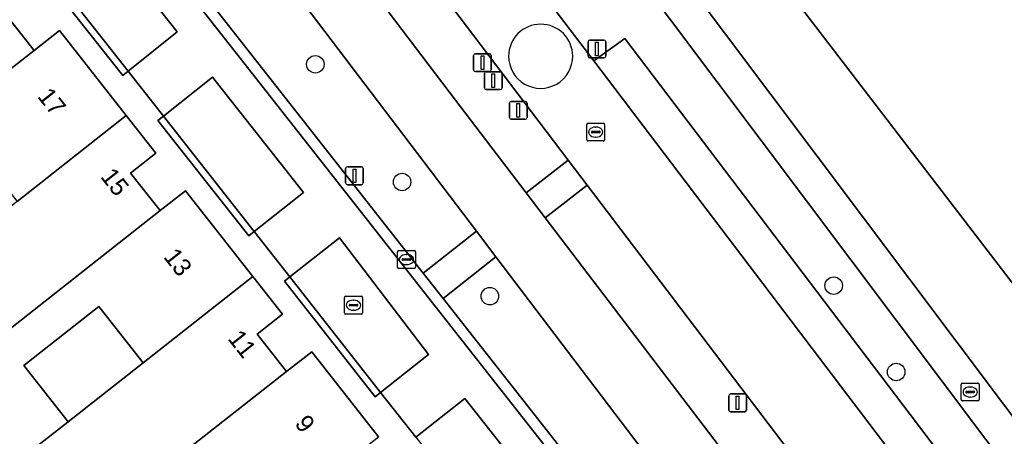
# Model space of a CAD drawing. Extents: x 156661 to 157576, y 383570 to 384425.
# Drawn here: x 157036.8 to 157091.8, y 383980.8 to 384004 of the extents above; entities that cross this region are included whole.
import ezdxf

# ---------------------------------------------------------------- set-up
doc = ezdxf.new("R2010")
doc.units = 0
for name, color, linetype in [('IMGEO_Afsluitpaal', 7, 'Continuous'), ('IMGEO_Berm_groen', 7, 'Continuous'), ('IMGEO_Boom', 7, 'Continuous'), ('IMGEO_Brandkraan', 7, 'Continuous'), ('IMGEO_Erf', 7, 'Continuous'), ('IMGEO_Fietspad_gesloten', 7, 'Continuous'), ('IMGEO_Groenvoorziening', 7, 'Continuous'), ('IMGEO_Kolk', 7, 'Continuous'), ('IMGEO_Lichtmast', 7, 'Continuous'), ('IMGEO_Muur', 7, 'Continuous'), ('IMGEO_Pand', 7, 'Continuous'), ('IMGEO_Pand_nummerreeks', 7, 'Continuous'), ('IMGEO_Parkeervlak_gesloten', 7, 'Continuous'), ('IMGEO_Rijbaan_lokaal_open', 7, 'Continuous'), ('IMGEO_Rioolput', 7, 'Continuous'), ('IMGEO_Voetpad_gesloten', 7, 'Continuous'), ('IMGEO_Voetpad_open', 7, 'Continuous')]:
    doc.layers.add(name, color=color, linetype=linetype)

msp = doc.modelspace()

# ---------------------------------------------------------------- linework, layer by layer
at = {"layer": 'IMGEO_Afsluitpaal'}
for p, q in [((157068.554, 384002.007), (157068.554, 384002.807)), ((157068.554, 384002.807), (157068.554, 384002.007)), ((157068.654, 384002.907), (157069.444, 384002.907)), ((157069.444, 384002.907), (157068.654, 384002.907)), ((157069.544, 384002.807), (157069.544, 384002.007)), ((157069.544, 384002.007), (157069.544, 384002.807)), ((157062.153, 384001.243), (157062.153, 384002.043)), ((157062.153, 384002.043), (157062.153, 384001.243)), ((157062.253, 384002.143), (157063.043, 384002.143)), ((157063.043, 384002.143), (157062.253, 384002.143)), ((157063.143, 384002.043), (157063.143, 384001.243)), ((157063.143, 384001.243), (157063.143, 384002.043)), ((157069.444, 384001.907), (157068.654, 384001.907)), ((157068.654, 384001.907), (157069.444, 384001.907)), ((157063.043, 384001.143), (157062.253, 384001.143)), ((157062.253, 384001.143), (157063.043, 384001.143)), ((157064.155, 383998.579), (157064.155, 383999.379)), ((157064.155, 383999.379), (157064.155, 383998.579)), ((157064.255, 383999.479), (157065.045, 383999.479)), ((157065.045, 383999.479), (157064.255, 383999.479)), ((157065.145, 383999.379), (157065.145, 383998.579)), ((157065.145, 383998.579), (157065.145, 383999.379)), ((157065.045, 383998.479), (157064.255, 383998.479)), ((157064.255, 383998.479), (157065.045, 383998.479))]:
    msp.add_line(p, q, dxfattribs=at)
for points in [[(157068.974, 384002.782), (157069.124, 384002.782), (157069.124, 384002.032), (157068.974, 384002.032), (157068.974, 384002.782)], [(157062.573, 384002.018), (157062.723, 384002.018), (157062.723, 384001.268), (157062.573, 384001.268), (157062.573, 384002.018)], [(157064.575, 383999.354), (157064.725, 383999.354), (157064.725, 383998.604), (157064.575, 383998.604), (157064.575, 383999.354)]]:
    msp.add_lwpolyline(points, dxfattribs=at)
for centre, start, end in [((157068.654, 384002.807), 90, 180), ((157068.654, 384002.807), 90, 180), ((157069.444, 384002.807), 0, 90), ((157069.444, 384002.807), 360, 90), ((157062.253, 384002.043), 90, 180), ((157062.253, 384002.043), 90, 180), ((157063.043, 384002.043), 0, 90), ((157063.043, 384002.043), 360, 90), ((157068.654, 384002.007), 180, 270), ((157068.654, 384002.007), 180, 270), ((157069.444, 384002.007), 270, 0), ((157069.444, 384002.007), 270, 0), ((157062.253, 384001.243), 180, 270), ((157062.253, 384001.243), 180, 270), ((157063.043, 384001.243), 270, 0), ((157063.043, 384001.243), 270, 0), ((157064.255, 383999.379), 90, 180), ((157064.255, 383999.379), 90, 180), ((157065.045, 383999.379), 0, 90), ((157065.045, 383999.379), 360, 90), ((157064.255, 383998.579), 180, 270), ((157064.255, 383998.579), 180, 270), ((157065.045, 383998.579), 270, 0), ((157065.045, 383998.579), 270, 0)]:
    msp.add_arc(centre, 0.1, start, end, dxfattribs=at)
at = {"layer": 'IMGEO_Berm_groen'}
for points in [[(157022.83, 384054.925), (157020.102, 384058.503), (157014.424, 384065.95), (157012.072, 384064.137), (157061.136, 383999.546), (157065.088, 383994.36), (157067.449, 383996.186), (157062.167, 384003.14)], [(157009.29, 384061.994), (157005.166, 384058.77), (157059.34, 383989.875), (157062.312, 383992.226)], [(157050.635, 384034.033), (157048.731, 384036.511), (157037.008, 384052.138), (157034.658, 384050.365), (157044.213, 384037.466), (157044.358, 384037.568), (157067.634, 384006.822), (157065.932, 384005.612), (157068.869, 384001.744), (157070.607, 384003.001), (157106.45, 383955.782), (157108.373, 383957.2)]]:
    msp.add_lwpolyline(points, close=True, dxfattribs=at)
for points in [[(157068.511, 383994.788), (157066.152, 383992.965), (157092.711, 383958.119)], [(157098.259, 383949.806), (157101.105, 383951.881), (157068.511, 383994.788)], [(157063.404, 383990.789), (157060.448, 383988.467), (157093.57, 383946.344), (157095.404, 383947.68)], [(157089.259, 383956.768), (157063.404, 383990.789)]]:
    msp.add_lwpolyline(points, dxfattribs=at)
at = {"layer": 'IMGEO_Boom'}
for centre in [(157053.305, 384001.553), (157058.156, 383994.971), (157082.287, 383989.179), (157063.064, 383988.589), (157085.787, 383984.352)]:
    msp.add_circle(centre, 0.489, dxfattribs=at)
at = {"layer": 'IMGEO_Brandkraan'}
for p, q in [((157089.496, 383983.733), (157090.348, 383983.733)), ((157089.421, 383982.807), (157089.421, 383983.659)), ((157089.68, 383983.227), (157089.68, 383983.239)), ((157090.118, 383983.19), (157089.72, 383983.19)), ((157089.723, 383983.276), (157090.121, 383983.276)), ((157089.909, 383983.513), (157089.934, 383983.513)), ((157090.164, 383983.239), (157090.164, 383983.227)), ((157090.422, 383983.659), (157090.422, 383982.807)), ((157090.348, 383982.733), (157089.496, 383982.733)), ((157089.932, 383982.953), (157089.907, 383982.953))]:
    msp.add_line(p, q, dxfattribs=at)
for points in [[(157089.496, 383983.733), (157090.348, 383983.733)], [(157089.421, 383982.807), (157089.421, 383983.659)], [(157090.422, 383983.659), (157090.422, 383982.807)], [(157090.348, 383982.733), (157089.496, 383982.733)]]:
    msp.add_lwpolyline(points, dxfattribs=at)
for centre, radius, start, end in [((157089.498, 383983.657), 0.0765, 91.552, 178.448), ((157089.498, 383983.657), 0.0765, 91.552, 178.448), ((157090.346, 383983.657), 0.0765, 1.552, 88.448), ((157090.346, 383983.657), 0.0765, 1.552, 88.448), ((157089.72, 383983.236), 0.0403, 85.8775, 175.7526), ((157089.717, 383983.226), 0.0366, 178.938, 274.7102), ((157090.121, 383983.233), 0.043, 264.8664, 352.4533), ((157090.125, 383983.238), 0.0386, 1.7309, 96.639), ((157089.498, 383982.809), 0.0765, 181.552, 268.448), ((157089.498, 383982.809), 0.0765, 181.552, 268.448), ((157090.346, 383982.809), 0.0765, 271.552, 358.448), ((157090.346, 383982.809), 0.0765, 271.552, 358.448)]:
    msp.add_arc(centre, radius, start, end, dxfattribs=at)
for centre, major_axis, ratio, start_param, end_param in [((157089.908, 383983.233), (-0.387, 0.002), 0.722429, 4.712389, 7.853982), ((157089.933, 383983.233), (-0.39, 0.002), 0.717154, 1.570796, 4.712389)]:
    msp.add_ellipse(centre, major_axis=major_axis, ratio=ratio, start_param=start_param, end_param=end_param, dxfattribs=at)
at = {"layer": 'IMGEO_Erf'}
for points in [[(157058.919, 383980.706), (157056.954, 383983.211), (157056.647, 383982.97), (157051.58, 383989.427), (157051.887, 383989.668), (157049.887, 383992.202), (157049.58, 383991.96), (157044.5, 383998.414), (157044.807, 383998.655), (157042.841, 384001.163), (157042.535, 384000.922), (157037.437, 384007.397)], [(157035.932, 384004.421), (157037.584, 384002.328), (157038.999, 384003.44), (157042.733, 383998.692), (157044.393, 383996.581), (157042.978, 383995.469), (157044.634, 383993.37), (157046.041, 383994.477), (157049.803, 383989.693), (157051.464, 383987.581), (157050.049, 383986.469), (157051.695, 383984.374), (157053.11, 383985.486), (157056.845, 383980.735)]]:
    msp.add_lwpolyline(points, dxfattribs=at)
msp.add_lwpolyline([(157039.483, 383981.571), (157043.672, 383984.868), (157041.198, 383988.011), (157037.01, 383984.714)], close=True, dxfattribs=at)
at = {"layer": 'IMGEO_Fietspad_gesloten'}
for points in [[(156992.1, 384084.489), (156997.679, 384077.272), (157008.067, 384063.603), (157009.29, 384061.994), (157062.312, 383992.226), (157063.404, 383990.789), (157089.259, 383956.768)], [(157092.711, 383958.119), (157066.152, 383992.965), (157065.088, 383994.36), (157061.136, 383999.546), (157012.072, 384064.137)]]:
    msp.add_lwpolyline(points, dxfattribs=at)
at = {"layer": 'IMGEO_Groenvoorziening'}
msp.add_lwpolyline([(157075.189, 384135.046), (157079.977, 384129.642), (157085.938, 384121.166), (157092.136, 384111.936), (157093.567, 384107.816), (157092.747, 384099.97), (157089.926, 384085.599), (157084.345, 384074.369), (157087.624, 384070.536), (157154.965, 383981.147), (157118.076, 383955.713), (157048.492, 384046.401), (157047.525, 384049.683), (157043.532, 384046.733), (157050.307, 384037.736), (157052.866, 384034.354), (157120.283, 383944.64), (157124.325, 383946.137), (157128.805, 383949.146), (157133.769, 383943.405), (157129.807, 383939.447), (157125.958, 383936.438), (157125.242, 383934.934), (157125.69, 383934.221)], dxfattribs=at)
for points in [[(157118.076, 383955.713), (157154.965, 383981.147), (157087.624, 384070.536), (157084.345, 384074.369), (157080.513, 384071.09), (157047.525, 384049.683), (157048.492, 384046.401)], [(157040.516, 384009.769), (157037.743, 384007.639), (157042.841, 384001.163), (157045.574, 384003.367)], [(157047.556, 384000.837), (157044.807, 383998.655), (157049.887, 383992.202), (157052.649, 383994.382)], [(157054.649, 383991.843), (157051.887, 383989.668), (157056.954, 383983.211), (157059.636, 383985.337)], [(157061.655, 383982.874), (157058.919, 383980.706), (157064.001, 383974.244), (157066.772, 383976.407)]]:
    msp.add_lwpolyline(points, close=True, dxfattribs=at)
at = {"layer": 'IMGEO_Kolk'}
for p, q in [((157057.9, 383990.211), (157057.9, 383991.063)), ((157057.975, 383991.137), (157058.827, 383991.137)), ((157058.388, 383990.917), (157058.413, 383990.917)), ((157058.901, 383991.063), (157058.901, 383990.211)), ((157058.159, 383990.631), (157058.159, 383990.643)), ((157058.597, 383990.594), (157058.199, 383990.594)), ((157058.202, 383990.68), (157058.6, 383990.68)), ((157058.411, 383990.357), (157058.386, 383990.357)), ((157058.643, 383990.643), (157058.643, 383990.631)), ((157058.827, 383990.137), (157057.975, 383990.137))]:
    msp.add_line(p, q, dxfattribs=at)
for points in [[(157057.9, 383990.211), (157057.9, 383991.063)], [(157057.975, 383991.137), (157058.827, 383991.137)], [(157058.901, 383991.063), (157058.901, 383990.211)], [(157058.827, 383990.137), (157057.975, 383990.137)]]:
    msp.add_lwpolyline(points, dxfattribs=at)
for centre, radius, start, end in [((157057.977, 383991.061), 0.0765, 91.552, 178.448), ((157057.977, 383991.061), 0.0765, 91.552, 178.448), ((157058.825, 383991.061), 0.0765, 1.552, 88.448), ((157058.825, 383991.061), 0.0765, 1.552, 88.448), ((157058.199, 383990.64), 0.0403, 85.8775, 175.7526), ((157058.196, 383990.63), 0.0366, 178.938, 274.7102), ((157058.6, 383990.637), 0.043, 264.8664, 352.4533), ((157058.604, 383990.642), 0.0386, 1.7309, 96.639), ((157057.977, 383990.213), 0.0765, 181.552, 268.448), ((157057.977, 383990.213), 0.0765, 181.552, 268.448), ((157058.825, 383990.213), 0.0765, 271.552, 358.448), ((157058.825, 383990.213), 0.0765, 271.552, 358.448)]:
    msp.add_arc(centre, radius, start, end, dxfattribs=at)
for centre, major_axis, ratio, start_param, end_param in [((157058.387, 383990.637), (-0.387, 0.002), 0.722429, 4.712389, 7.853982), ((157058.412, 383990.637), (-0.39, 0.002), 0.717154, 1.570796, 4.712389)]:
    msp.add_ellipse(centre, major_axis=major_axis, ratio=ratio, start_param=start_param, end_param=end_param, dxfattribs=at)
at = {"layer": 'IMGEO_Lichtmast'}
for p, q in [((157062.757, 384000.235), (157062.757, 384001.035)), ((157062.757, 384001.035), (157062.757, 384000.235)), ((157062.857, 384001.135), (157063.647, 384001.135)), ((157063.647, 384001.135), (157062.857, 384001.135)), ((157063.747, 384001.035), (157063.747, 384000.235)), ((157063.747, 384000.235), (157063.747, 384001.035)), ((157063.647, 384000.135), (157062.857, 384000.135)), ((157062.857, 384000.135), (157063.647, 384000.135)), ((157054.996, 383994.922), (157054.996, 383995.722)), ((157054.996, 383995.722), (157054.996, 383994.922)), ((157055.096, 383995.822), (157055.886, 383995.822)), ((157055.886, 383995.822), (157055.096, 383995.822)), ((157055.986, 383995.722), (157055.986, 383994.922)), ((157055.986, 383994.922), (157055.986, 383995.722)), ((157055.886, 383994.822), (157055.096, 383994.822)), ((157055.096, 383994.822), (157055.886, 383994.822)), ((157076.422, 383982.224), (157076.422, 383983.024)), ((157076.422, 383983.024), (157076.422, 383982.224)), ((157076.522, 383983.124), (157077.312, 383983.124)), ((157077.312, 383983.124), (157076.522, 383983.124)), ((157077.412, 383983.024), (157077.412, 383982.224)), ((157077.412, 383982.224), (157077.412, 383983.024)), ((157077.312, 383982.124), (157076.522, 383982.124)), ((157076.522, 383982.124), (157077.312, 383982.124))]:
    msp.add_line(p, q, dxfattribs=at)
for points in [[(157063.177, 384001.01), (157063.327, 384001.01), (157063.327, 384000.26), (157063.177, 384000.26), (157063.177, 384001.01)], [(157055.416, 383995.697), (157055.566, 383995.697), (157055.566, 383994.947), (157055.416, 383994.947), (157055.416, 383995.697)], [(157076.842, 383982.999), (157076.992, 383982.999), (157076.992, 383982.249), (157076.842, 383982.249), (157076.842, 383982.999)]]:
    msp.add_lwpolyline(points, dxfattribs=at)
for centre, start, end in [((157062.857, 384001.035), 90, 180), ((157062.857, 384001.035), 90, 180), ((157063.647, 384001.035), 0, 90), ((157063.647, 384001.035), 360, 90), ((157062.857, 384000.235), 180, 270), ((157062.857, 384000.235), 180, 270), ((157063.647, 384000.235), 270, 0), ((157063.647, 384000.235), 270, 0), ((157055.096, 383995.722), 90, 180), ((157055.096, 383995.722), 90, 180), ((157055.886, 383995.722), 0, 90), ((157055.886, 383995.722), 360, 90), ((157055.096, 383994.922), 180, 270), ((157055.096, 383994.922), 180, 270), ((157055.886, 383994.922), 270, 0), ((157055.886, 383994.922), 270, 0), ((157076.522, 383983.024), 90, 180), ((157076.522, 383983.024), 90, 180), ((157077.312, 383983.024), 0, 90), ((157077.312, 383983.024), 360, 90), ((157076.522, 383982.224), 180, 270), ((157076.522, 383982.224), 180, 270), ((157077.312, 383982.224), 270, 0), ((157077.312, 383982.224), 270, 0)]:
    msp.add_arc(centre, 0.1, start, end, dxfattribs=at)
at = {"layer": 'IMGEO_Muur'}
for points in [[(157037.743, 384007.639), (157037.437, 384007.397), (157042.535, 384000.922), (157042.841, 384001.163)], [(157044.807, 383998.655), (157044.5, 383998.414), (157049.58, 383991.96), (157049.887, 383992.202)], [(157051.887, 383989.668), (157051.58, 383989.427), (157056.647, 383982.97), (157056.954, 383983.211)]]:
    msp.add_lwpolyline(points, close=True, dxfattribs=at)
at = {"layer": 'IMGEO_Pand'}
for points in [[(157037.584, 384002.328), (157035.932, 384004.421), (157037.347, 384005.534), (157035.684, 384007.648), (157029.582, 384002.846), (157025.375, 383999.535), (157022.984, 383997.653), (157026.276, 383993.464)], [(157036.625, 383993.885), (157042.733, 383998.692), (157038.999, 384003.44), (157037.584, 384002.328), (157026.276, 383993.464), (157021.992, 383990.098), (157022.216, 383989.804), (157022.401, 383989.945), (157025.728, 383985.775), (157025.516, 383985.608), (157025.745, 383985.318), (157030.022, 383988.688), (157032.369, 383990.535), (157029.919, 383993.648), (157034.175, 383996.998)], [(157044.634, 383993.37), (157042.978, 383995.469), (157044.393, 383996.581), (157042.733, 383998.692), (157036.625, 383993.885), (157032.369, 383990.535), (157030.022, 383988.688), (157033.325, 383984.498)], [(157043.672, 383984.868), (157049.803, 383989.693), (157046.041, 383994.477), (157044.634, 383993.37), (157033.325, 383984.498), (157029.036, 383981.139), (157029.261, 383980.846), (157029.468, 383981.005), (157032.788, 383976.809), (157032.568, 383976.652), (157032.805, 383976.321), (157037.106, 383979.7), (157039.483, 383981.571), (157037.01, 383984.714), (157041.198, 383988.011)], [(157051.695, 383984.374), (157050.049, 383986.469), (157051.464, 383987.581), (157049.803, 383989.693), (157043.672, 383984.868), (157039.483, 383981.571), (157037.106, 383979.7), (157040.402, 383975.505)], [(157050.739, 383975.93), (157056.845, 383980.735), (157053.11, 383985.486), (157051.695, 383984.374), (157040.402, 383975.505), (157036.106, 383972.141), (157036.331, 383971.847), (157036.555, 383972.018), (157039.84, 383967.818), (157039.63, 383967.648), (157039.859, 383967.365), (157044.124, 383970.724), (157046.559, 383972.64), (157044.156, 383975.694), (157048.336, 383978.984)]]:
    msp.add_lwpolyline(points, close=True, dxfattribs=at)
at = {"layer": 'IMGEO_Parkeervlak_gesloten'}
msp.add_lwpolyline([(157106.45, 383955.782), (157070.607, 384003.001), (157068.869, 384001.744), (157104.737, 383954.519)], close=True, dxfattribs=at)
at = {"layer": 'IMGEO_Rijbaan_lokaal_open'}
msp.add_lwpolyline([(157022.83, 384054.925), (157062.167, 384003.14), (157067.449, 383996.186), (157068.511, 383994.788), (157101.105, 383951.881), (157104.737, 383954.519), (157068.869, 384001.744), (157065.932, 384005.612), (157050.224, 384026.292), (157048.783, 384028.189), (157046.346, 384031.399), (157042.601, 384036.329), (157033.137, 384048.791)], dxfattribs=at)
for start, end in [(0.016, 179.984), (0.016, 179.984), (179.984, 0.016), (179.984, 0.016)]:
    msp.add_arc((157065.905, 384002), 1.794, start, end, dxfattribs=at)
at = {"layer": 'IMGEO_Rioolput'}
for p, q in [((157068.481, 383997.338), (157068.481, 383998.19)), ((157068.556, 383998.264), (157069.408, 383998.264)), ((157069.482, 383998.19), (157069.482, 383997.338)), ((157068.74, 383997.758), (157068.74, 383997.77)), ((157069.178, 383997.721), (157068.78, 383997.721)), ((157068.783, 383997.807), (157069.181, 383997.807)), ((157068.969, 383998.044), (157068.994, 383998.044)), ((157069.224, 383997.77), (157069.224, 383997.758)), ((157069.408, 383997.264), (157068.556, 383997.264)), ((157068.992, 383997.484), (157068.967, 383997.484)), ((157054.938, 383987.66), (157054.938, 383988.512)), ((157055.013, 383988.586), (157055.865, 383988.586)), ((157055.426, 383988.366), (157055.451, 383988.366)), ((157055.939, 383988.512), (157055.939, 383987.66)), ((157055.197, 383988.08), (157055.197, 383988.092)), ((157055.635, 383988.043), (157055.237, 383988.043)), ((157055.24, 383988.129), (157055.638, 383988.129)), ((157055.449, 383987.806), (157055.424, 383987.806)), ((157055.681, 383988.092), (157055.681, 383988.08)), ((157055.865, 383987.586), (157055.013, 383987.586))]:
    msp.add_line(p, q, dxfattribs=at)
for points in [[(157068.481, 383997.338), (157068.481, 383998.19)], [(157068.556, 383998.264), (157069.408, 383998.264)], [(157069.482, 383998.19), (157069.482, 383997.338)], [(157069.408, 383997.264), (157068.556, 383997.264)], [(157054.938, 383987.66), (157054.938, 383988.512)], [(157055.013, 383988.586), (157055.865, 383988.586)], [(157055.939, 383988.512), (157055.939, 383987.66)], [(157055.865, 383987.586), (157055.013, 383987.586)]]:
    msp.add_lwpolyline(points, dxfattribs=at)
for centre, radius, start, end in [((157068.558, 383998.188), 0.0765, 91.552, 178.448), ((157068.558, 383998.188), 0.0765, 91.552, 178.448), ((157069.406, 383998.188), 0.0765, 1.552, 88.448), ((157069.406, 383998.188), 0.0765, 1.552, 88.448), ((157068.78, 383997.767), 0.0403, 85.8775, 175.7526), ((157068.777, 383997.757), 0.0366, 178.938, 274.7102), ((157069.181, 383997.764), 0.043, 264.8664, 352.4533), ((157069.185, 383997.769), 0.0386, 1.7309, 96.639), ((157068.558, 383997.34), 0.0765, 181.552, 268.448), ((157068.558, 383997.34), 0.0765, 181.552, 268.448), ((157069.406, 383997.34), 0.0765, 271.552, 358.448), ((157069.406, 383997.34), 0.0765, 271.552, 358.448), ((157055.015, 383988.51), 0.0765, 91.552, 178.448), ((157055.015, 383988.51), 0.0765, 91.552, 178.448), ((157055.863, 383988.51), 0.0765, 1.552, 88.448), ((157055.863, 383988.51), 0.0765, 1.552, 88.448), ((157055.015, 383987.662), 0.0765, 181.552, 268.448), ((157055.015, 383987.662), 0.0765, 181.552, 268.448), ((157055.237, 383988.089), 0.0403, 85.8775, 175.7526), ((157055.234, 383988.079), 0.0366, 178.938, 274.7102), ((157055.638, 383988.086), 0.043, 264.8664, 352.4533), ((157055.642, 383988.091), 0.0386, 1.7309, 96.639), ((157055.863, 383987.662), 0.0765, 271.552, 358.448), ((157055.863, 383987.662), 0.0765, 271.552, 358.448)]:
    msp.add_arc(centre, radius, start, end, dxfattribs=at)
for centre, major_axis, ratio, start_param, end_param in [((157068.968, 383997.764), (-0.387, 0.002), 0.722429, 4.712389, 7.853982), ((157068.993, 383997.764), (-0.39, 0.002), 0.717154, 1.570796, 4.712389), ((157055.425, 383988.086), (-0.387, 0.002), 0.722429, 4.712389, 7.853982), ((157055.45, 383988.086), (-0.39, 0.002), 0.717154, 1.570796, 4.712389)]:
    msp.add_ellipse(centre, major_axis=major_axis, ratio=ratio, start_param=start_param, end_param=end_param, dxfattribs=at)
at = {"layer": 'IMGEO_Voetpad_gesloten'}
msp.add_lwpolyline([(157040.516, 384009.769), (157045.574, 384003.367), (157042.841, 384001.163), (157044.807, 383998.655), (157047.556, 384000.837), (157052.649, 383994.382), (157049.887, 383992.202), (157051.887, 383989.668), (157054.649, 383991.843), (157059.636, 383985.337), (157056.954, 383983.211), (157058.919, 383980.706), (157061.655, 383982.874), (157066.772, 383976.407), (157064.001, 383974.244), (157065.96, 383971.742), (157068.728, 383973.903), (157073.818, 383967.471), (157071.046, 383965.29), (157072.009, 383964.052), (157074.729, 383966.297), (157091.566, 383944.874), (157093.064, 383945.973), (157004.709, 384058.354)], dxfattribs=at)
at = {"layer": 'IMGEO_Voetpad_open'}
msp.add_lwpolyline([(157034.658, 384050.365), (157037.008, 384052.138), (157048.731, 384036.511), (157050.635, 384034.033), (157108.373, 383957.2), (157106.45, 383955.782), (157104.737, 383954.519), (157105.699, 383953.252), (157109.313, 383955.948), (157118.349, 383943.924), (157120.283, 383944.64), (157052.866, 384034.354), (157050.307, 384037.736), (157043.532, 384046.733), (157027.895, 384067.5)], dxfattribs=at)
for points in [[(157059.34, 383989.875), (157005.166, 384058.77), (157004.709, 384058.354), (157093.064, 383945.973), (157093.57, 383946.344), (157060.448, 383988.467)], [(157068.511, 383994.788), (157067.449, 383996.186), (157065.088, 383994.36), (157066.152, 383992.965)], [(157063.404, 383990.789), (157062.312, 383992.226), (157059.34, 383989.875), (157060.448, 383988.467)]]:
    msp.add_lwpolyline(points, close=True, dxfattribs=at)

# ---------------------------------------------------------------- texts
at = {"layer": 'IMGEO_Pand_nummerreeks'}
for s, p in [('17', (157037.723, 383999.744)), ('15', (157041.249, 383995.26)), ('13', (157044.775, 383990.776)), ('11', (157048.37, 383986.205)), ('9', (157052.11, 383981.448))]:
    msp.add_text(s, height=1, rotation=308.1817, dxfattribs=at).set_placement(p)

doc.saveas('drawing.dxf')
